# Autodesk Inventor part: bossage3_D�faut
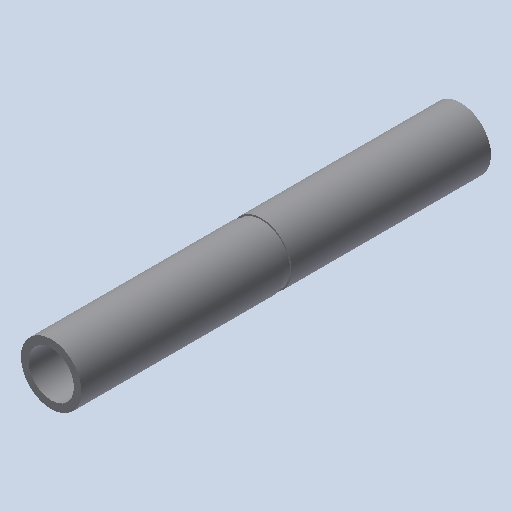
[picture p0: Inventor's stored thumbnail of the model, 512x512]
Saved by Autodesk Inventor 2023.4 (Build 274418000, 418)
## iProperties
Created: 2011-01
Part Number: bossage3_D�faut
Document SubType Name: Modeling
Designer: eric
Density: 1 g/cm^3
Mass: 1.18262 g
Surface Area: 24.2757 cm^2
Volume: 1.18262 cm^3
Material: Générique
Appearance: Par défaut
Author: eric
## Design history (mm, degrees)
feature "Base1"
node "Corps solides"
node "Corps surfaciques"
node "Solide1"
